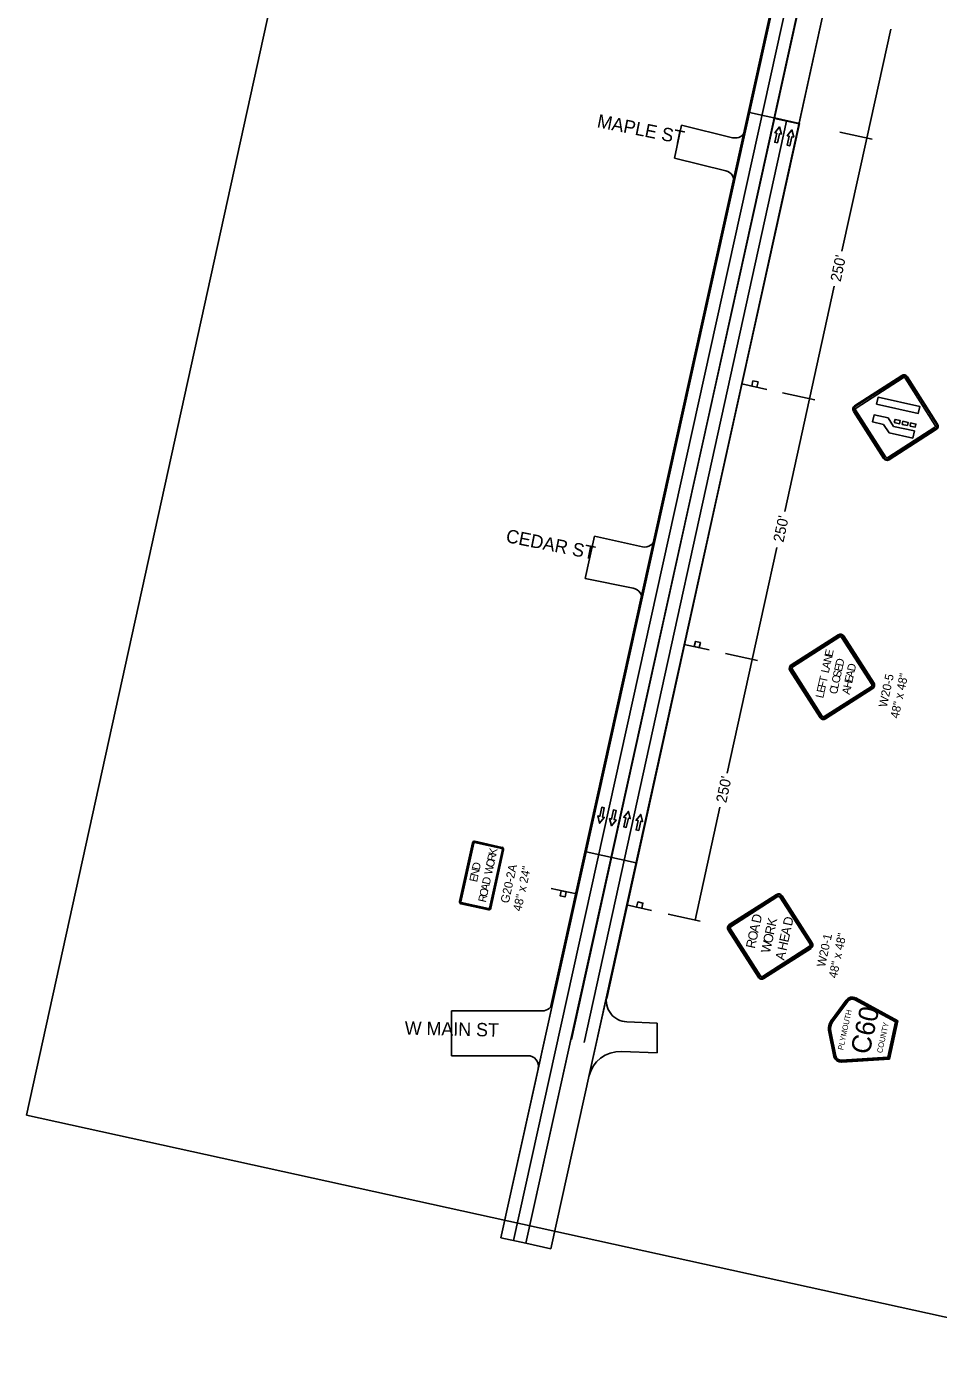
# Model space of a CAD drawing. Extents: x 14104283 to 14129344, y 8637090 to 8673339.
# Drawn here: x 14106925 to 14107780, y 8637090 to 8638327 of the extents above; entities that cross this region are included whole.
import ezdxf

# ---------------------------------------------------------------- set-up
doc = ezdxf.new("R2010")
doc.units = 0
for name, color, linetype in [('Cell', 7, 'Continuous'), ('Default', 7, 'Continuous'), ('dsnNonPlotable', 7, 'Continuous'), ('dsnPaintExistingBrokenLaneLineWhite', 7, 'Continuous'), ('dsnPaintExistingDoubleCenterYellow', 7, 'Continuous'), ('dsnPaintExistingEdgeLineRightWhite', 7, 'Continuous'), ('dsnStdLabel', 7, 'Continuous'), ('dsnTextOverlapOdd', 7, 'Continuous'), ('Sign', 7, 'Continuous')]:
    doc.layers.add(name, color=color, linetype=linetype)

msp = doc.modelspace()

# ---------------------------------------------------------------- linework, layer by layer
at = {"layer": 'Cell'}
for p, q in [((14107700.9, 8637971.4), (14107745.1, 8637999.7)), ((14107745.1, 8637999.7), (14107700.9, 8637971.4)), ((14107701.4, 8637970.6), (14107745.6, 8637998.9)), ((14107746.4, 8637997.6), (14107702.2, 8637969.3)), ((14107776.5, 8637953), (14107748.2, 8637997.2)), ((14107749.5, 8637998.1), (14107777.8, 8637953.8)), ((14107750.3, 8637998.6), (14107778.6, 8637954.3)), ((14107778.6, 8637954.3), (14107750.3, 8637998.6)), ((14107618.6, 8637986.8), (14107595.1, 8637991.9)), ((14107728, 8637922), (14107699.7, 8637966.2)), ((14107699.7, 8637966.2), (14107728, 8637922)), ((14107699.7, 8637966.2), (14107699.7, 8637966.2)), ((14107728.8, 8637922.5), (14107700.5, 8637966.7)), ((14107701.8, 8637967.6), (14107701.8, 8637967.6)), ((14107701.8, 8637967.6), (14107730.1, 8637923.4)), ((14107731.9, 8637923), (14107776.1, 8637951.3)), ((14107776.9, 8637950), (14107732.7, 8637921.7)), ((14107777.4, 8637949.2), (14107733.2, 8637920.9)), ((14107733.2, 8637920.9), (14107777.4, 8637949.2)), ((14107685.6, 8637756.9), (14107641.4, 8637728.6)), ((14107686.1, 8637756.1), (14107686.9, 8637754.8)), ((14107688.7, 8637754.4), (14107690, 8637755.3)), ((14107719.1, 8637711.6), (14107690.8, 8637755.8)), ((14107564.6, 8637742.7), (14107541.2, 8637747.8)), ((14107641, 8637724), (14107642.3, 8637724.8)), ((14107642.7, 8637726.5), (14107641.9, 8637727.8)), ((14107640.2, 8637723.4), (14107668.5, 8637679.2)), ((14107673.7, 8637678.1), (14107717.9, 8637706.4)), ((14107716.6, 8637708.5), (14107717.4, 8637707.2)), ((14107718.3, 8637711.1), (14107717, 8637710.2)), ((14107670.6, 8637680.6), (14107669.3, 8637679.7)), ((14107673.2, 8637678.9), (14107672.4, 8637680.2)), ((14107370.6, 8637557.7), (14107345, 8637563.4)), ((14107342.8, 8637561.9), (14107330.7, 8637507)), ((14107343.2, 8637561.8), (14107344, 8637561.7)), ((14107344.7, 8637562.2), (14107344.9, 8637562.9)), ((14107360, 8637500.6), (14107372.1, 8637555.5)), ((14107370.5, 8637557.3), (14107370.4, 8637556.5)), ((14107370.9, 8637555.8), (14107371.6, 8637555.6)), ((14107416.7, 8637519.2), (14107440.2, 8637514.1)), ((14107331.9, 8637506.7), (14107331.2, 8637506.9)), ((14107332.1, 8637504.8), (14107357.8, 8637499.1)), ((14107332.2, 8637505.2), (14107332.4, 8637506)), ((14107510.7, 8637498.5), (14107487.3, 8637503.7)), ((14107627.7, 8637513.6), (14107583.5, 8637485.3)), ((14107628.2, 8637512.8), (14107629.1, 8637511.5)), ((14107630.8, 8637511.1), (14107632.1, 8637511.9)), ((14107661.2, 8637468.2), (14107632.9, 8637512.4)), ((14107358, 8637500.4), (14107357.9, 8637499.6)), ((14107359.5, 8637500.7), (14107358.8, 8637500.8)), ((14107582.4, 8637480.1), (14107610.7, 8637435.9)), ((14107583.2, 8637480.6), (14107584.5, 8637481.4)), ((14107584.9, 8637483.2), (14107584, 8637484.5)), ((14107658.7, 8637465.1), (14107659.6, 8637463.8)), ((14107660.4, 8637467.7), (14107659.1, 8637466.9)), ((14107615.8, 8637434.7), (14107660.1, 8637463)), ((14107612.8, 8637437.2), (14107611.5, 8637436.4)), ((14107615.3, 8637435.5), (14107614.5, 8637436.8))]:
    msp.add_line(p, q, dxfattribs=at)
for points in [[(14107628.6, 8638217.8), (14107626.1, 8638218.3), (14107628, 8638226.8), (14107626.2, 8638227.2), (14107630.6, 8638232.7), (14107632.3, 8638225.9), (14107630.4, 8638226.3)], [(14107640.2, 8638214.9), (14107637.8, 8638215.5), (14107639.6, 8638224), (14107637.8, 8638224.4), (14107642.2, 8638229.9), (14107643.9, 8638223.1), (14107642.1, 8638223.5)], [(14107604.6, 8637989.9), (14107609.4, 8637988.9), (14107610.4, 8637993.7), (14107605.6, 8637994.7)], [(14107721.4, 8637972.8), (14107760.5, 8637964.2), (14107761.9, 8637970.8), (14107722.9, 8637979.4)], [(14107728.1, 8637954), (14107733.2, 8637946.1), (14107755.4, 8637941.2), (14107756.9, 8637947.8), (14107737.4, 8637952.1), (14107732.3, 8637960), (14107719.2, 8637962.9), (14107717.8, 8637956.3)], [(14107738.1, 8637955.7), (14107738.8, 8637958.6), (14107743.7, 8637957.5), (14107743, 8637954.6)], [(14107745.5, 8637954), (14107746.1, 8637957), (14107751, 8637955.9), (14107750.3, 8637953)], [(14107752.8, 8637952.4), (14107753.4, 8637955.4), (14107758.3, 8637954.3), (14107757.7, 8637951.4)], [(14107550.6, 8637745.8), (14107555.4, 8637744.8), (14107556.5, 8637749.6), (14107551.7, 8637750.6)], [(14107686.1, 8637756.1), (14107641.9, 8637727.8), (14107642.7, 8637726.5), (14107686.9, 8637754.8), (14107686.1, 8637756.1)], [(14107718.3, 8637711.1), (14107690, 8637755.3), (14107688.7, 8637754.4), (14107717, 8637710.2), (14107718.3, 8637711.1)], [(14107641, 8637724), (14107669.3, 8637679.7), (14107670.6, 8637680.6), (14107642.3, 8637724.8), (14107641, 8637724)], [(14107673.2, 8637678.9), (14107717.4, 8637707.2), (14107716.6, 8637708.5), (14107672.4, 8637680.2), (14107673.2, 8637678.9)], [(14107464, 8637595.2), (14107466.4, 8637594.7), (14107464.6, 8637586.1), (14107466.4, 8637585.7), (14107462, 8637580.3), (14107460.3, 8637587.1), (14107462.1, 8637586.7)], [(14107475, 8637592.8), (14107477.5, 8637592.2), (14107475.6, 8637583.7), (14107477.4, 8637583.3), (14107473.1, 8637577.9), (14107471.3, 8637584.6), (14107473.2, 8637584.2)], [(14107487, 8637576.4), (14107484.6, 8637577), (14107486.4, 8637585.5), (14107484.6, 8637585.9), (14107489, 8637591.3), (14107490.7, 8637584.6), (14107488.9, 8637585)], [(14107498.6, 8637573.6), (14107496.2, 8637574.1), (14107498.1, 8637582.7), (14107496.2, 8637583.1), (14107500.6, 8637588.5), (14107502.3, 8637581.8), (14107500.5, 8637582.2)], [(14107343.2, 8637561.8), (14107331.2, 8637506.9), (14107331.9, 8637506.7), (14107344, 8637561.7), (14107343.2, 8637561.8)], [(14107370.5, 8637557.3), (14107344.9, 8637562.9), (14107344.7, 8637562.2), (14107370.4, 8637556.5), (14107370.5, 8637557.3)], [(14107359.5, 8637500.7), (14107371.6, 8637555.6), (14107370.9, 8637555.8), (14107358.8, 8637500.8), (14107359.5, 8637500.7)], [(14107430.7, 8637516), (14107425.9, 8637517.1), (14107424.9, 8637512.3), (14107429.7, 8637511.3)], [(14107332.2, 8637505.2), (14107357.9, 8637499.6), (14107358, 8637500.4), (14107332.4, 8637506), (14107332.2, 8637505.2)], [(14107496.7, 8637501.7), (14107501.5, 8637500.7), (14107502.6, 8637505.5), (14107497.8, 8637506.5)], [(14107628.2, 8637512.8), (14107584, 8637484.5), (14107584.9, 8637483.2), (14107629.1, 8637511.5), (14107628.2, 8637512.8)], [(14107660.4, 8637467.7), (14107632.1, 8637511.9), (14107630.8, 8637511.1), (14107659.1, 8637466.9), (14107660.4, 8637467.7)], [(14107583.2, 8637480.6), (14107611.5, 8637436.4), (14107612.8, 8637437.2), (14107584.5, 8637481.4), (14107583.2, 8637480.6)], [(14107615.3, 8637435.5), (14107659.6, 8637463.8), (14107658.7, 8637465.1), (14107614.5, 8637436.8), (14107615.3, 8637435.5)]]:
    msp.add_lwpolyline(points, close=True, dxfattribs=at)
for points in [[(14107630.4, 8638226.3), (14107632.3, 8638225.9), (14107630.6, 8638232.7), (14107626.2, 8638227.2), (14107628, 8638226.8), (14107626.1, 8638218.3), (14107628.6, 8638217.8), (14107630.4, 8638226.3)], [(14107642.1, 8638223.5), (14107643.9, 8638223.1), (14107642.2, 8638229.9), (14107637.8, 8638224.4), (14107639.6, 8638224), (14107637.8, 8638215.5), (14107640.2, 8638214.9), (14107642.1, 8638223.5)], [(14107745.6, 8637998.9), (14107701.4, 8637970.6)], [(14107746.4, 8637997.6), (14107702.2, 8637969.3)], [(14107776.5, 8637953), (14107748.2, 8637997.2)], [(14107777.8, 8637953.8), (14107749.5, 8637998.1)], [(14107604.6, 8637989.9), (14107609.4, 8637988.9), (14107610.4, 8637993.7), (14107605.6, 8637994.7), (14107604.6, 8637989.9)], [(14107700.5, 8637966.7), (14107728.8, 8637922.5)], [(14107701.8, 8637967.6), (14107730.1, 8637923.4)], [(14107731.9, 8637923), (14107776.1, 8637951.3)], [(14107732.7, 8637921.7), (14107776.9, 8637950)], [(14107550.6, 8637745.8), (14107555.4, 8637744.8), (14107556.5, 8637749.6), (14107551.7, 8637750.6), (14107550.6, 8637745.8)], [(14107462.1, 8637586.7), (14107460.3, 8637587.1), (14107462, 8637580.3), (14107466.4, 8637585.7), (14107464.6, 8637586.1), (14107466.4, 8637594.7), (14107464, 8637595.2), (14107462.1, 8637586.7)], [(14107473.2, 8637584.2), (14107471.3, 8637584.6), (14107473.1, 8637577.9), (14107477.4, 8637583.3), (14107475.6, 8637583.7), (14107477.5, 8637592.2), (14107475, 8637592.8), (14107473.2, 8637584.2)], [(14107488.9, 8637585), (14107490.7, 8637584.6), (14107489, 8637591.3), (14107484.6, 8637585.9), (14107486.4, 8637585.5), (14107484.6, 8637577), (14107487, 8637576.4), (14107488.9, 8637585)], [(14107500.5, 8637582.2), (14107502.3, 8637581.8), (14107500.6, 8637588.5), (14107496.2, 8637583.1), (14107498.1, 8637582.7), (14107496.2, 8637574.1), (14107498.6, 8637573.6), (14107500.5, 8637582.2)], [(14107430.7, 8637516), (14107425.9, 8637517.1), (14107424.9, 8637512.3), (14107429.7, 8637511.3), (14107430.7, 8637516)], [(14107496.7, 8637501.7), (14107501.5, 8637500.7), (14107502.6, 8637505.5), (14107497.8, 8637506.5), (14107496.7, 8637501.7)]]:
    msp.add_lwpolyline(points, dxfattribs=at)
for centre, radius, start, end in [((14107747.1, 8637996.6), 3.75, 32.6103, 122.6105), ((14107747.1, 8637996.6), 3.75, 32.6103, 122.6105), ((14107747.1, 8637996.6), 2.81, 32.6103, 122.6105), ((14107747.1, 8637996.6), 2.81, 32.6103, 122.6105), ((14107747.1, 8637996.6), 1.25, 32.6103, 122.6105), ((14107747.1, 8637996.6), 1.25, 32.6103, 122.6105), ((14107702.9, 8637968.3), 3.75, 122.6105, 212.6102), ((14107702.9, 8637968.3), 3.75, 122.6105, 212.6102), ((14107702.9, 8637968.3), 2.81, 122.6105, 212.6102), ((14107702.9, 8637968.3), 2.81, 122.6105, 212.6102), ((14107702.9, 8637968.3), 1.25, 122.6105, 212.6102), ((14107702.9, 8637968.3), 1.25, 122.6105, 212.6102), ((14107775.4, 8637952.3), 1.25, 302.61, 32.6103), ((14107775.4, 8637952.3), 1.25, 302.61, 32.6103), ((14107775.4, 8637952.3), 2.81, 302.61, 32.6103), ((14107775.4, 8637952.3), 2.81, 302.61, 32.6103), ((14107775.4, 8637952.3), 3.75, 302.61, 32.6103), ((14107775.4, 8637952.3), 3.75, 302.61, 32.6103), ((14107731.2, 8637924), 3.75, 212.6104, 302.61), ((14107731.2, 8637924), 3.75, 212.6104, 302.61), ((14107731.2, 8637924), 2.81, 212.6104, 302.61), ((14107731.2, 8637924), 2.81, 212.6104, 302.61), ((14107731.2, 8637924), 1.25, 212.6104, 302.61), ((14107731.2, 8637924), 1.25, 212.6104, 302.61), ((14107687.6, 8637753.8), 3.75, 32.6104, 122.61), ((14107687.6, 8637753.8), 2.81, 32.6104, 122.61), ((14107687.6, 8637753.8), 1.25, 32.6104, 122.61), ((14107643.4, 8637725.5), 3.75, 122.6102, 212.61), ((14107643.4, 8637725.5), 2.81, 122.6102, 212.61), ((14107643.4, 8637725.5), 1.25, 122.6102, 212.61), ((14107715.9, 8637709.5), 1.25, 302.6102, 32.6104), ((14107715.9, 8637709.5), 2.81, 302.6102, 32.6104), ((14107715.9, 8637709.5), 3.75, 302.6102, 32.6104), ((14107671.7, 8637681.2), 3.75, 212.61, 302.6102), ((14107671.7, 8637681.2), 2.81, 212.61, 302.6102), ((14107671.7, 8637681.2), 1.25, 212.61, 302.6102), ((14107344.6, 8637561.5), 1.87, 77.6102, 167.6104), ((14107344.6, 8637561.5), 1.41, 77.6102, 167.6104), ((14107344.6, 8637561.5), 0.625, 77.6102, 167.6104), ((14107370.2, 8637555.9), 0.625, 347.6103, 77.6105), ((14107370.2, 8637555.9), 1.41, 347.6103, 77.6105), ((14107370.2, 8637555.9), 1.87, 347.6103, 77.6105), ((14107629.8, 8637510.4), 3.75, 32.6104, 122.61), ((14107332.5, 8637506.6), 1.87, 167.6104, 257.6101), ((14107332.5, 8637506.6), 1.41, 167.6104, 257.6101), ((14107332.5, 8637506.6), 0.625, 167.6104, 257.6101), ((14107629.8, 8637510.4), 2.81, 32.6104, 122.61), ((14107629.8, 8637510.4), 1.25, 32.6104, 122.61), ((14107358.2, 8637501), 1.87, 257.6101, 347.6103), ((14107358.2, 8637501), 1.41, 257.6101, 347.6103), ((14107358.2, 8637501), 0.625, 257.6101, 347.6103), ((14107585.5, 8637482.1), 3.75, 122.6102, 212.61), ((14107585.5, 8637482.1), 2.81, 122.6102, 212.61), ((14107585.5, 8637482.1), 1.25, 122.6102, 212.61), ((14107658, 8637466.2), 1.25, 302.6102, 32.6104), ((14107658, 8637466.2), 2.81, 302.6102, 32.6104), ((14107658, 8637466.2), 3.75, 302.6102, 32.6104), ((14107613.8, 8637437.9), 3.75, 212.61, 302.6102), ((14107613.8, 8637437.9), 2.81, 212.61, 302.6102), ((14107613.8, 8637437.9), 1.25, 212.61, 302.6102)]:
    msp.add_arc(centre, radius, start, end, dxfattribs=at)
at = {"layer": 'Default'}
for p, q in [((14107625.5, 8638241.2), (14107678, 8638480.1)), ((14107701.4, 8638474.9), (14107648.9, 8638236.1)), ((14107532.2, 8638203.4), (14107538.8, 8638234.3)), ((14107538.8, 8638234.3), (14107586.6, 8638222.6)), ((14107649.2, 8638236), (14107625.8, 8638241.2)), ((14107598.8, 8638230.1), (14107587.6, 8638179.7)), ((14107580.3, 8638191.6), (14107532.2, 8638203.4)), ((14107457.3, 8637849.2), (14107448.6, 8637809.7)), ((14107502.2, 8637839.3), (14107457.3, 8637849.2)), ((14107501.3, 8637788.6), (14107514.1, 8637846.9)), ((14107448.6, 8637809.7), (14107493.5, 8637800.6)), ((14107452, 8637342.9), (14107468.7, 8637418.5)), ((14107323.2, 8637404.5), (14107408.4, 8637404.5)), ((14107323.2, 8637362.5), (14107323.2, 8637404.5)), ((14107418.2, 8637412.3), (14107404.5, 8637350.3)), ((14107487.5, 8637394.2), (14107516, 8637393.1)), ((14107516, 8637393.1), (14107516, 8637365.1)), ((14107516, 8637365.1), (14107482.4, 8637366.4)), ((14107394.7, 8637362.5), (14107323.2, 8637362.5))]:
    msp.add_line(p, q, dxfattribs=at)
for points in [[(14107392.9, 8637186.7), (14107369.5, 8637191.9), (14107655.1, 8638485.1), (14107678.5, 8638480)], [(14107602.3, 8638246.3), (14107649.2, 8638236), (14107496.2, 8637543.2), (14107449.3, 8637553.5)], [(14107416.4, 8637181.6), (14107649.1, 8638235.5), (14107625.7, 8638240.7), (14107392.9, 8637186.7)]]:
    msp.add_lwpolyline(points, close=True, dxfattribs=at)
for centre, radius, start, end in [((14107589, 8638232.3), 10, 256.2115, 347.5463), ((14107577.9, 8638181.9), 10, 347.5463, 76.2115), ((14107504.4, 8637849.1), 10, 257.5811, 347.5463), ((14107491.5, 8637790.8), 10, 347.5463, 78.5027), ((14107488.2, 8637414.2), 20, 167.5463, 267.8178), ((14107408.4, 8637414.5), 10, 270, 347.5463), ((14107481.3, 8637336.4), 30, 87.8178, 167.5463), ((14107394.7, 8637352.5), 10, 347.5463, 90)]:
    msp.add_arc(centre, radius, start, end, dxfattribs=at)
at = {"layer": 'dsnNonPlotable'}
msp.add_lwpolyline([(14106925, 8637306.7), (14107261.4, 8638837.7), (14108247.8, 8638620.9), (14107911.4, 8637089.9)], close=True, dxfattribs=at)
at = {"layer": 'dsnPaintExistingBrokenLaneLineWhite'}
for p, q in [((14107381.2, 8637189.3), (14107721.8, 8638731.5)), ((14107447.5, 8637375), (14107637.1, 8638238.2))]:
    msp.add_line(p, q, dxfattribs=at)
at = {"layer": 'dsnPaintExistingDoubleCenterYellow'}
msp.add_line((14107435.8, 8637377.6), (14107678, 8638480.1), dxfattribs=at)
at = {"layer": 'dsnPaintExistingEdgeLineRightWhite'}
for p, q in [((14107468.8, 8637416), (14107828.5, 8639053.6)), ((14107708.9, 8638734.4), (14107415.9, 8637407.6)), ((14107406.8, 8637361.1), (14107369.5, 8637191.9))]:
    msp.add_line(p, q, dxfattribs=at)
at = {"layer": 'dsnStdLabel'}
for p, q in [((14107712.3, 8638222.2), (14107734.7, 8638324.3)), ((14107717.2, 8638221.1), (14107687.1, 8638227.7)), ((14107689, 8638116.2), (14107712.3, 8638222.2)), ((14107658.7, 8637978), (14107681.8, 8638083.5)), ((14107663.5, 8637976.9), (14107633.4, 8637983.5)), ((14107635.5, 8637872.5), (14107658.7, 8637978)), ((14107605, 8637733.8), (14107628.1, 8637838.7)), ((14107609.9, 8637732.7), (14107579.8, 8637739.3)), ((14107581.6, 8637627.2), (14107605, 8637733.8)), ((14107551.4, 8637489.6), (14107574.6, 8637595.5)), ((14107556.3, 8637488.5), (14107526.2, 8637495.2))]:
    msp.add_line(p, q, dxfattribs=at)
at = {"layer": 'Sign'}
for p, q in [((14107701, 8637414.9), (14107739.2, 8637394.2)), ((14107739.2, 8637394.2), (14107701, 8637414.9)), ((14107740.3, 8637394.7), (14107701.4, 8637415.7)), ((14107701.4, 8637415.7), (14107740.3, 8637394.7)), ((14107701.9, 8637416.6), (14107741.4, 8637395.2)), ((14107679.1, 8637395.8), (14107693, 8637414.6)), ((14107693.8, 8637414), (14107679.8, 8637395.2)), ((14107679.8, 8637395.2), (14107693.8, 8637414)), ((14107680.6, 8637394.6), (14107694.6, 8637413.4)), ((14107694.6, 8637413.4), (14107680.6, 8637394.6)), ((14107739.2, 8637394.2), (14107731.9, 8637361.1)), ((14107731.9, 8637361.1), (14107739.2, 8637394.2)), ((14107732.7, 8637360.2), (14107740.3, 8637394.7)), ((14107740.3, 8637394.7), (14107732.7, 8637360.2)), ((14107741.4, 8637395.2), (14107733.5, 8637359.3)), ((14107741.4, 8637395.2), (14107740.3, 8637394.7)), ((14107681.5, 8637361.8), (14107676.6, 8637384.7)), ((14107677.6, 8637384.9), (14107682.4, 8637362)), ((14107682.4, 8637362), (14107677.6, 8637384.9)), ((14107683.4, 8637362.2), (14107678.5, 8637385.1)), ((14107678.5, 8637385.1), (14107683.4, 8637362.2)), ((14107731.9, 8637361.1), (14107688.6, 8637358.3)), ((14107688.6, 8637358.3), (14107731.9, 8637361.1)), ((14107688.7, 8637357.3), (14107732.7, 8637360.2)), ((14107732.7, 8637360.2), (14107688.7, 8637357.3)), ((14107733.5, 8637359.3), (14107688.8, 8637356.3)), ((14107731.9, 8637361.1), (14107732.7, 8637360.2))]:
    msp.add_line(p, q, dxfattribs=at)
for centre, radius, start, end in [((14107698.6, 8637410.4), 6.97, 61.5883, 143.4611), ((14107698.6, 8637410.4), 5.99, 61.5883, 143.4611), ((14107698.6, 8637410.4), 5.99, 61.5883, 143.4611), ((14107698.6, 8637410.4), 5.02, 61.5883, 143.4611), ((14107698.6, 8637410.4), 5.02, 61.5883, 143.4611), ((14107690.1, 8637387.6), 13.8, 143.4611, 191.9213), ((14107690.1, 8637387.6), 12.8, 143.4611, 191.9213), ((14107690.1, 8637387.6), 12.8, 143.4611, 191.9213), ((14107690.1, 8637387.6), 11.8, 143.4611, 191.9213), ((14107690.1, 8637387.6), 11.8, 143.4611, 191.9213), ((14107688.3, 8637363.3), 6.97, 191.9213, 273.7941), ((14107688.3, 8637363.3), 5.99, 191.9213, 273.7941), ((14107688.3, 8637363.3), 5.99, 191.9213, 273.7941), ((14107688.3, 8637363.3), 5.02, 191.9213, 273.7941), ((14107688.3, 8637363.3), 5.02, 191.9213, 273.7941)]:
    msp.add_arc(centre, radius, start, end, dxfattribs=at)

# ---------------------------------------------------------------- texts
at = {"layer": 'Cell'}
for s, height, p in [('N', 7.5, (14107678.8, 8637730.4)), ('E', 7.5, (14107680, 8637735.9)), ('L', 7.5, (14107676.6, 8637720.5)), ('A', 7.5, (14107677.5, 8637724.5)), ('E', 7.5, (14107688.9, 8637721.9)), ('D', 7.5, (14107690, 8637726.8)), ('D', 7.5, (14107701, 8637722.1)), ('F', 7.5, (14107673.6, 8637706.8)), ('T', 7.5, (14107674.6, 8637711.3)), ('O', 7.5, (14107686.5, 8637710.9)), ('S', 7.5, (14107687.7, 8637716.3)), ('H', 7.5, (14107697.5, 8637706.2)), ('E', 7.5, (14107698.7, 8637711.8)), ('A', 7.5, (14107699.7, 8637716.3)), ('W20-5', 8, (14107731, 8637688.4)), ('48" x 48"', 8, (14107742, 8637678)), ('L', 7.5, (14107671.5, 8637697)), ('E', 7.5, (14107672.5, 8637701.9)), ('C', 7.5, (14107684.3, 8637700.7)), ('L', 7.5, (14107685.4, 8637706)), ('A', 7.5, (14107696.2, 8637700.4)), ('R', 7.5, (14107363.8, 8637544.1)), ('K', 7.5, (14107365, 8637549.7)), ('D', 7.5, (14107349.5, 8637535.8)), ('W', 7.5, (14107361.1, 8637531.7)), ('O', 7.5, (14107362.6, 8637538.4)), ('G20-2A', 8, (14107376.8, 8637504.8)), ('48" x 24"', 8, (14107388.5, 8637497.3)), ('E', 7.5, (14107347.1, 8637524.7)), ('N', 7.5, (14107348.2, 8637529.9)), ('D', 7.5, (14107359, 8637522.2)), ('O', 7.5, (14107356.5, 8637511)), ('A', 7.5, (14107357.7, 8637516.4)), ('R', 7.5, (14107355.4, 8637505.7)), ('D', 8.75, (14107612.6, 8637486)), ('K', 8.75, (14107626.9, 8637483)), ('D', 8.75, (14107642.1, 8637483.5)), ('O', 8.75, (14107609, 8637469.7)), ('A', 8.75, (14107610.6, 8637477.3)), ('O', 8.75, (14107623.5, 8637467.2)), ('R', 8.75, (14107625.2, 8637475.2)), ('E', 8.75, (14107638.7, 8637468.2)), ('A', 8.75, (14107640.1, 8637474.6)), ('48" x 48"', 8, (14107684.1, 8637434.6)), ('R', 8.75, (14107607.4, 8637462.4)), ('W', 8.75, (14107621.5, 8637458.1)), ('H', 8.75, (14107637, 8637460.3)), ('W20-1', 8, (14107673.1, 8637445.1)), ('A', 8.75, (14107635, 8637451.4))]:
    msp.add_text(s, height=height, rotation=77.6102, dxfattribs=at).set_placement(p)
at = {"layer": 'dsnStdLabel'}
for p in [(14107687.8, 8638087.1), (14107634.2, 8637842.9), (14107580.6, 8637598.8)]:
    msp.add_text("250'", height=10, rotation=78.0531, dxfattribs=at).set_placement(p)
at = {"layer": 'dsnTextOverlapOdd'}
for s, rotation, p in [('MAPLE ST', 348.6912, (14107458.9, 8638232.5)), ('CEDAR ST', 348.6912, (14107373.5, 8637843.8)), ('W MAIN ST', 358.6912, (14107279.3, 8637382.3))]:
    msp.add_text(s, height=12.5, rotation=rotation, dxfattribs=at).set_placement(p)
at = {"layer": 'Sign'}
for s, height, p in [('PLYMOUTH', 5.18, (14107690.1, 8637367.4)), ('C60', 18.14, (14107714.6, 8637362.8)), ('COUNTY', 5.18, (14107726.7, 8637364.6))]:
    msp.add_text(s, height=height, rotation=77.6912, dxfattribs=at).set_placement(p)

doc.saveas('drawing.dxf')
